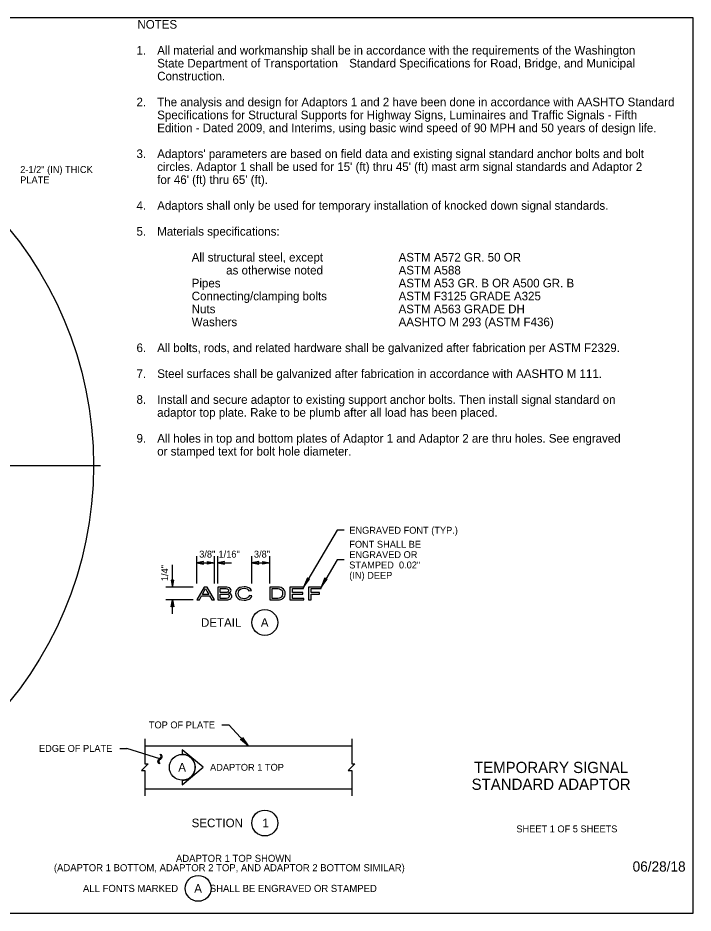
# Model space of a CAD drawing. Extents: x 99862 to 103151, y 100000 to 114076.
# Drawn here: x 101585 to 103151, y 100000 to 102076 of the extents above; entities that cross this region are included whole.
import ezdxf

# ---------------------------------------------------------------- set-up
doc = ezdxf.new("R2010")
doc.units = 0
for name, color, linetype in [('Level 1', 7, 'Continuous'), ('Level 14', 7, 'Continuous'), ('Level 15', 7, 'Continuous'), ('Level 20', 7, 'Continuous'), ('Level 60', 7, 'Continuous'), ('Level 62', 7, 'Continuous')]:
    doc.layers.add(name, color=color, linetype=linetype)

msp = doc.modelspace()

# ---------------------------------------------------------------- linework, layer by layer
at = {"layer": 'Level 1'}
msp.add_lwpolyline([(99862, 99999.5), (103151, 99999.5), (103151, 102075.5), (99862, 102075.5)], close=True, dxfattribs=at)
at = {"layer": 'Level 14'}
for p, q in [((101879, 100387.6), (102359, 100387.6)), ((101879, 100287.6), (102359, 100287.6))]:
    msp.add_line(p, q, dxfattribs=at)
at = {"layer": 'Level 15'}
for p, q in [((102325.4, 100887.3), (102247.3, 100755.6)), ((102341.4, 100887.3), (102325.4, 100887.3)), ((101999.6, 100763.6), (101999.6, 100827.6)), ((101999.6, 100811.6), (102040.7, 100811.6)), ((102040.7, 100763.6), (102040.7, 100827.6)), ((102048.3, 100763.6), (102048.3, 100827.6)), ((102048.3, 100811.6), (102080.3, 100811.6)), ((102127.7, 100763.6), (102127.7, 100827.6)), ((102127.7, 100811.6), (102168.8, 100811.6)), ((102168.8, 100763.6), (102168.8, 100827.6)), ((102325.4, 100818.8), (102287.9, 100755.6)), ((102341.4, 100818.8), (102325.4, 100818.8)), ((101943.6, 100755.6), (101943.6, 100807.1)), ((101991.6, 100755.6), (101927.6, 100755.6)), ((101991.6, 100725.7), (101927.6, 100725.7)), ((101943.6, 100693.7), (101943.6, 100725.7)), ((102058.1, 100436), (102074.1, 100436)), ((102119, 100387.6), (102074.1, 100436)), ((101879, 100403.6), (101879, 100361.4)), ((102359, 100403.6), (102359, 100361.4)), ((101821.3, 100381.4), (101837.3, 100381.4)), ((101914.2, 100357.1), (101837.3, 100381.4)), ((101910, 100353.2), (101911.2, 100355.6)), ((101911.2, 100355.6), (101914.2, 100358.8)), ((101912.8, 100353.9), (101911.9, 100352.2)), ((101914.5, 100355.8), (101912.8, 100353.9)), ((101914.2, 100358.8), (101915.9, 100360.6)), ((101917.4, 100358.7), (101914.5, 100355.8)), ((101916.4, 100365), (101914.8, 100368.3)), ((101914.8, 100368.3), (101916.8, 100367.6)), ((101915.9, 100360.6), (101916.6, 100362)), ((101916.7, 100363.4), (101916.4, 100365)), ((101916.6, 100362), (101916.7, 100363.4)), ((101916.8, 100367.6), (101917.9, 100365.8)), ((101918.5, 100360.9), (101917.4, 100358.7)), ((101917.9, 100365.8), (101918.6, 100364.2)), ((101918.8, 100362.6), (101918.5, 100360.9)), ((101918.6, 100364.2), (101918.8, 100362.6)), ((101909.7, 100351.5), (101910, 100353.2)), ((101909.8, 100349.8), (101909.7, 100351.5)), ((101910.5, 100348.1), (101909.8, 100349.8)), ((101911.7, 100346.5), (101910.5, 100348.1)), ((101911.9, 100352.2), (101911.7, 100350.9)), ((101911.7, 100350.9), (101911.8, 100349.5)), ((101913.7, 100345.8), (101911.7, 100346.5)), ((101911.8, 100349.5), (101912.5, 100347.9)), ((101912.5, 100347.9), (101913.7, 100345.8)), ((101879, 100313.9), (101879, 100271.6)), ((102359, 100313.9), (102359, 100271.6))]:
    msp.add_line(p, q, dxfattribs=at)
for points in [[(101999.6, 100811.6), (102015.3, 100808.5), (102014.6, 100811.6), (102015.3, 100814.7)], [(102040.7, 100811.6), (102024.9, 100808.5), (102025.7, 100811.6), (102024.9, 100814.7)], [(102048.3, 100811.6), (102064, 100808.5), (102063.3, 100811.6), (102064, 100814.7)], [(102127.7, 100811.6), (102143.4, 100808.5), (102142.7, 100811.6), (102143.4, 100814.7)], [(102168.8, 100811.6), (102153, 100808.5), (102153.8, 100811.6), (102153, 100814.7)], [(101943.6, 100755.6), (101946.6, 100771.3), (101943.6, 100770.6), (101940.5, 100771.3)], [(102247.3, 100755.6), (102261.5, 100773.7), (102258.4, 100774.3), (102256.3, 100776.7)], [(102287.9, 100755.6), (102302.1, 100773.7), (102299, 100774.3), (102297, 100776.7)], [(102121.6, 100736.2), (102120, 100732.9), (102117.2, 100730.5), (102113.7, 100729.1), (102109.4, 100728.6), (102105.6, 100728.9), (102102.2, 100730), (102099.4, 100731.8), (102097.4, 100734.2), (102096.2, 100737.3), (102095.8, 100740.9), (102096.1, 100743.8), (102097.1, 100746.6), (102098.9, 100749.1), (102101.6, 100751.1), (102105.2, 100752.3), (102109.6, 100752.7), (102113.5, 100752.3), (102116.6, 100751.2), (102119, 100749.3), (102120.8, 100746.5), (102126.8, 100747.4), (102125.8, 100749.3), (102124.4, 100751.1), (102122.7, 100752.6), (102120.7, 100753.8), (102118.4, 100754.8), (102115.8, 100755.6), (102113, 100756), (102109.9, 100756.1), (102104.5, 100755.7), (102099.6, 100754.3), (102095.4, 100752.1), (102092.3, 100749), (102090.4, 100745.3), (102089.8, 100740.9), (102090.3, 100736.7), (102092, 100732.8), (102094.8, 100729.5), (102098.6, 100727.1), (102103.6, 100725.7), (102109.9, 100725.2), (102113.1, 100725.3), (102116.1, 100725.8), (102118.8, 100726.6), (102121.2, 100727.7), (102123.4, 100729.2), (102125.2, 100730.9), (102126.6, 100732.9), (102127.7, 100735.2)], [(102215.4, 100725.7), (102248.1, 100725.7), (102248.1, 100729.2), (102221.4, 100729.2), (102221.4, 100739.5), (102245.5, 100739.5), (102245.5, 100742.9), (102221.4, 100742.9), (102221.4, 100752.1), (102247.3, 100752.1), (102247.3, 100755.6), (102215.4, 100755.6)], [(102258.6, 100725.7), (102264.7, 100725.7), (102264.7, 100739.5), (102284.5, 100739.5), (102284.5, 100742.9), (102264.7, 100742.9), (102264.7, 100752.1), (102287.9, 100752.1), (102287.9, 100755.6), (102258.6, 100755.6)], [(101943.6, 100725.7), (101946.6, 100710), (101943.6, 100710.7), (101940.5, 100710)], [(102119, 100387.6), (102101.3, 100402.3), (102104.2, 100403.6), (102105.6, 100406.4)]]:
    msp.add_lwpolyline(points, close=True, dxfattribs=at)
for points in [[(101999.6, 100725.7), (102005.9, 100725.7), (102010.8, 100734.9), (102029.4, 100734.9), (102034.3, 100725.7), (102040.7, 100725.7), (102023.7, 100755.6), (102016.5, 100755.6), (101999.6, 100725.7)], [(102012.7, 100738.4), (102017.1, 100746.6), (102020.1, 100752.1), (102023.3, 100746.1), (102027.5, 100738.4), (102012.7, 100738.4)], [(102048.3, 100725.7), (102064.8, 100725.7), (102068.6, 100725.9), (102071.8, 100726.2), (102074.4, 100726.9), (102076.5, 100727.7), (102078.3, 100728.9), (102079.7, 100730.5), (102080.7, 100732.4), (102081, 100734.5), (102080.4, 100736.9), (102078.9, 100739.1), (102076.3, 100740.7), (102072.8, 100741.8), (102075.6, 100743), (102077.7, 100744.5), (102078.9, 100746.2), (102079.3, 100748), (102078.8, 100750), (102077.5, 100751.9), (102075.5, 100753.5), (102072.8, 100754.7), (102069.2, 100755.4), (102064.7, 100755.6), (102048.3, 100755.6), (102048.3, 100725.7)], [(102054.3, 100742.9), (102054.3, 100752.1), (102062.8, 100752.1), (102066.7, 100752), (102069.3, 100751.7), (102071, 100751.1), (102072.2, 100750.1), (102073, 100748.9), (102073.2, 100747.5), (102073, 100746), (102072.1, 100744.8), (102070.8, 100743.9), (102068.9, 100743.3), (102063.5, 100742.9), (102054.3, 100742.9)], [(102168.8, 100725.7), (102184.5, 100725.7), (102191.6, 100726.2), (102194.4, 100726.9), (102196.8, 100727.7), (102198.8, 100728.9), (102200.8, 100730.4), (102202.4, 100732.4), (102203.8, 100734.8), (102204.6, 100737.6), (102204.9, 100740.8), (102204.5, 100744.6), (102203.2, 100747.9), (102201, 100750.7), (102198, 100753), (102195.1, 100754.3), (102191.6, 100755.1), (102183.8, 100755.6), (102168.8, 100755.6), (102168.8, 100725.7)], [(102174.8, 100729.2), (102174.8, 100752.1), (102183.9, 100752.1), (102188.2, 100752), (102191.3, 100751.5), (102194.2, 100750.2), (102196.7, 100748.1), (102198.3, 100745), (102198.9, 100740.9), (102198.6, 100737.7), (102197.7, 100735.1), (102196.4, 100732.9), (102194.6, 100731.3), (102192.9, 100730.4), (102190.7, 100729.7), (102187.8, 100729.3), (102184, 100729.2), (102174.8, 100729.2)], [(102054.3, 100729.2), (102054.3, 100739.5), (102064.2, 100739.5), (102067.7, 100739.4), (102070.4, 100739), (102072.3, 100738.3), (102073.8, 100737.3), (102074.6, 100735.9), (102075, 100734.3), (102074.7, 100733), (102074.1, 100731.8), (102072, 100730.1), (102068.7, 100729.3), (102064.9, 100729.2), (102054.3, 100729.2)], [(101879, 100361.4), (101879, 100345.4), (101886.7, 100345.4), (101871.2, 100329.9), (101879, 100329.9), (101879, 100313.9)], [(102359, 100361.4), (102359, 100345.4), (102366.7, 100345.4), (102351.2, 100329.9), (102359, 100329.9), (102359, 100313.9)]]:
    msp.add_lwpolyline(points, dxfattribs=at)
at = {"layer": 'Level 20'}
for p, q in [((100010.7, 101037.5), (101776.3, 101037.5)), ((101966.1, 100378.2), (101966.1, 100367.6)), ((102014.5, 100337.6), (101966.1, 100378.2)), ((101966.1, 100297), (102014.5, 100337.6)), ((101966.1, 100307.6), (101966.1, 100297))]:
    msp.add_line(p, q, dxfattribs=at)
for centre, radius in [((100893.5, 101037.5), 866.8), ((102157.4, 100673.4), 30), ((101966.1, 100337.6), 30), ((102157.4, 100208.4), 30), ((102003, 100056.8), 30)]:
    msp.add_circle(centre, radius, dxfattribs=at)
msp.add_arc((101966.1, 100337.6), 30, 269.9978, 90.0022, dxfattribs=at)
at = {"layer": 'Level 60'}
msp.add_line((103151, 102075.5), (103151, 102075.5), dxfattribs=at)

# ---------------------------------------------------------------- texts
at = {"layer": 'Level 15'}
msp.add_text('06/28/18', height=23.62, dxfattribs=at).set_placement((103010.7, 100095.8))
at = {"layer": 'Level 20'}
for s, height, p in [('NOTES', 20, (101862, 102050.5)), ('1.', 20, (101859.9, 101990.5)), ('All material and workmanship shall be in accordance with the requirements of the Washington ', 20, (101907.9, 101990.5)), ('State Department of Transportation ', 20, (101907.9, 101960.5)), ('Standard Specifications for Road, Bridge, and Municipal ', 20, (102353.3, 101960.5)), ('Construction. ', 20, (101907.9, 101930.5)), ('2.', 20, (101859.9, 101870.5)), ('The analysis and design for Adaptors 1 and 2 have been done in accordance with AASHTO Standard ', 20, (101907.9, 101870.5)), ('Specifications for Structural Supports for Highway Signs, Luminaires and Traffic Signals - Fifth ', 20, (101907.9, 101840.5)), ('Edition - Dated 2009, and Interims, using basic wind speed of 90 MPH and 50 years of design life.', 20, (101907.9, 101810.5)), ('3.', 20, (101859.9, 101750.5)), ("Adaptors' parameters are based on field data and existing signal standard anchor bolts and bolt ", 20, (101907.9, 101750.5)), ('2-1/2" (IN) THICK ', 16, (101590.2, 101715.9)), ("circles. Adaptor 1 shall be used for 15' (ft) thru 45' (ft) mast arm signal standards and Adaptor 2 ", 20, (101907.9, 101720.5)), ('PLATE', 16, (101590.2, 101691.9)), ("for 46' (ft) thru 65' (ft).", 20, (101907.9, 101690.5)), ('4.', 20, (101859.9, 101630.5)), ('Adaptors shall only be used for temporary installation of knocked down signal standards. ', 20, (101907.9, 101630.5)), ('5.', 20, (101859.9, 101570.5)), ('Materials specifications:', 20, (101907.9, 101570.5)), ('All structural steel, except ', 20, (101987.9, 101510.5)), ('ASTM A572 GR. 50 OR', 20, (102467.9, 101510.5)), ('as otherwise noted', 20, (102067.9, 101480.5)), ('ASTM A588', 20, (102467.9, 101480.5)), ('Pipes', 20, (101987.9, 101450.5)), ('ASTM A53 GR. B OR A500 GR. B', 20, (102467.9, 101450.5)), ('Connecting/clamping bolts', 20, (101987.9, 101420.5)), ('ASTM F3125 GRADE A325', 20, (102467.9, 101420.5)), ('Nuts', 20, (101987.9, 101390.5)), ('ASTM A563 GRADE DH', 20, (102467.9, 101390.5)), ('Washers', 20, (101987.9, 101360.5)), ('AASHTO M 293 (ASTM F436)', 20, (102467.9, 101360.5)), ('6.', 20, (101859.9, 101300.5)), ('All bolts, rods, and related hardware shall be galvanized after fabrication per ASTM F2329.', 20, (101907.9, 101300.5)), ('7.', 20, (101859.9, 101240.5)), ('Steel surfaces shall be galvanized after fabrication in accordance with AASHTO M 111.', 20, (101907.9, 101240.5)), ('8.', 20, (101859.9, 101180.5)), ('Install and secure adaptor to existing support anchor bolts. Then install signal standard on ', 20, (101907.9, 101180.5)), ('adaptor top plate. Rake to be plumb after all load has been placed. ', 20, (101907.9, 101150.5)), ('9.', 20, (101859.9, 101090.5)), ('All holes in top and bottom plates of Adaptor 1 and Adaptor 2 are thru holes. See engraved ', 20, (101907.9, 101090.5)), ('or stamped text for bolt hole diameter. ', 20, (101907.9, 101060.5)), ('ENGRAVED FONT (TYP.)', 16, (102353.4, 100879.3)), ('FONT SHALL BE ', 16, (102353.4, 100846.8)), ('3/8"', 16, (102005.3, 100823.9)), ('1/16"', 16, (102050.1, 100823.9)), ('3/8"', 16, (102132.2, 100823.9)), ('ENGRAVED OR', 16, (102353.4, 100822.8)), ('STAMPED  0.02"', 16, (102353.4, 100798.8)), ('(IN) DEEP', 16, (102353.4, 100774.8)), ('DETAIL', 20, (102009.4, 100663.4)), ('A', 20, (102148.3, 100663.4)), ('TOP OF PLATE', 16, (101888.5, 100428)), ('EDGE OF PLATE', 16, (101633.6, 100373.4)), ('A', 20, (101956.8, 100327.6)), ('ADAPTOR 1 TOP', 16, (102030.5, 100329.6)), ('SECTION', 20, (101987.8, 100198.6)), ('1', 20, (102151.8, 100198.4)), ('ADAPTOR 1 TOP SHOWN', 16.5, (101951.4, 100118.2)), ('(ADAPTOR 1 BOTTOM, ADAPTOR 2 TOP, AND ADAPTOR 2 BOTTOM SIMILAR)', 16.5, (101668.2, 100096.5)), ('ALL FONTS MARKED            SHALL BE ENGRAVED OR STAMPED', 16.5, (101735.7, 100048.5)), ('A', 20, (101993.8, 100046.8))]:
    msp.add_text(s, height=height, dxfattribs=at).set_placement(p)
msp.add_text('1/4"', height=16, rotation=90, dxfattribs=at).set_placement((101933.2, 100769.4))
at = {"layer": 'Level 62'}
for s, height, p in [('TEMPORARY SIGNAL ', 26, (102642.8, 100324.3)), ('STANDARD ADAPTOR', 26, (102637.2, 100285.3)), ('SHEET 1 OF 5 SHEETS', 16, (102741.1, 100186.8))]:
    msp.add_text(s, height=height, dxfattribs=at).set_placement(p)

doc.saveas('drawing.dxf')
